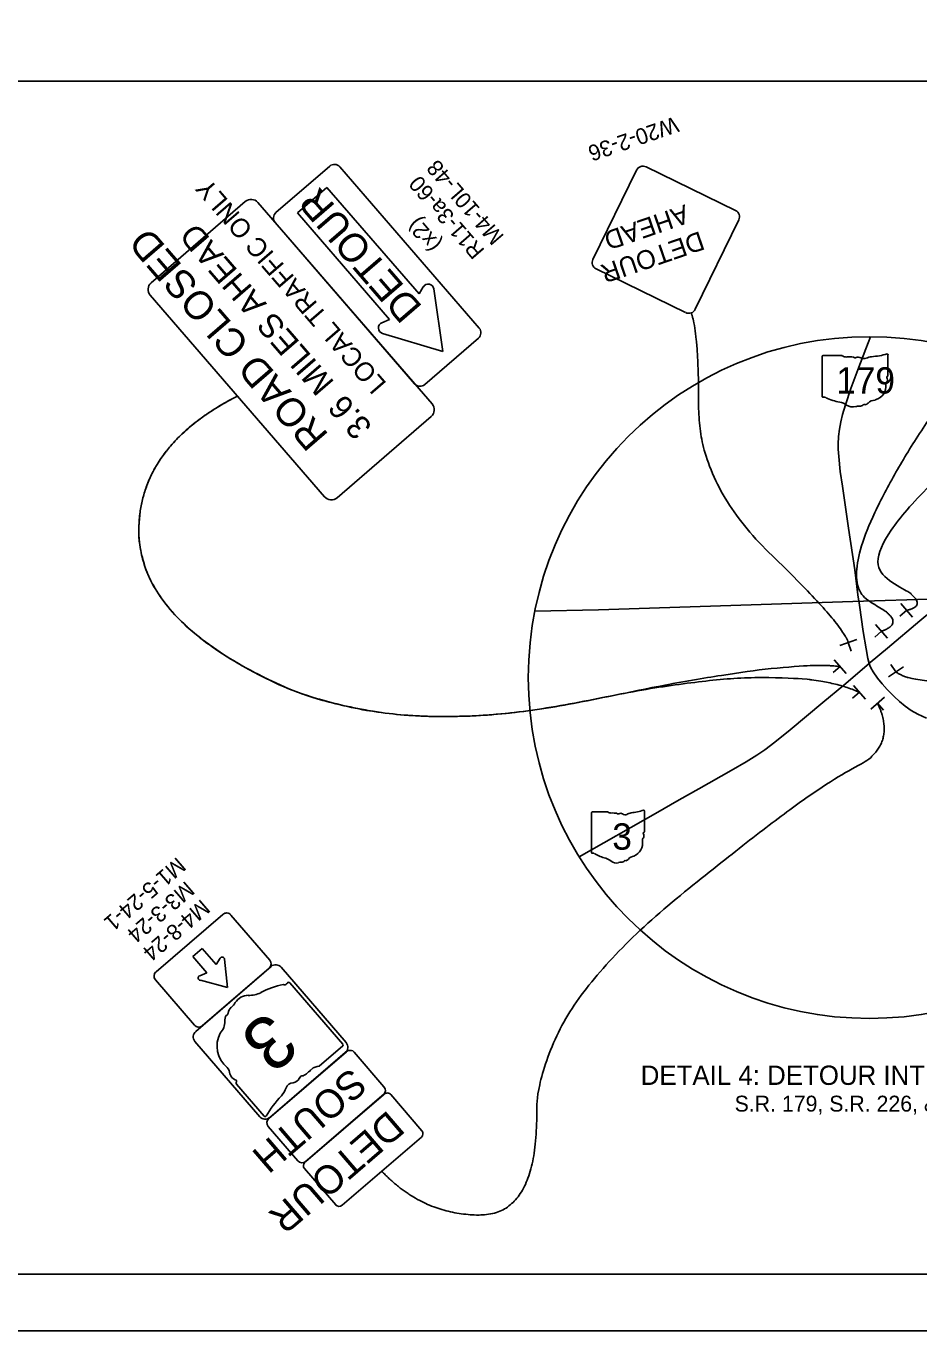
# Model space of a CAD drawing. Extents: x -15.3 to 34, y 0 to 22.
# Drawn here: x 16.96 to 24.81, y 0 to 11.48 of the extents above; entities that cross this region are included whole.
import ezdxf

# ---------------------------------------------------------------- set-up
doc = ezdxf.new("R2010")
doc.units = 0
for name, color, linetype in [('GM_X_State_Route', 7, 'Continuous'), ('GM_X_State_Shield', 7, 'Continuous'), ('GM_X_Township', 7, 'Continuous'), ('SC_Scratch1', 7, 'Continuous'), ('SH_Border', 7, 'Continuous'), ('SH_Cut_Line', 7, 'Continuous'), ('SH_Text', 7, 'Continuous'), ('SN_P_Signs', 7, 'Continuous')]:
    doc.layers.add(name, color=color, linetype=linetype)

msp = doc.modelspace()

# ---------------------------------------------------------------- linework, layer by layer
at = {"layer": 'GM_X_State_Route'}
for points in [[(24.275, 6.479), (24.248, 6.699), (24.193, 7.066), (24.138, 7.434), (24.119, 7.564), (24.106, 7.695), (24.101, 7.761), (24.101, 7.805), (24.104, 7.871), (24.113, 7.937), (24.124, 8.001), (24.14, 8.066), (24.164, 8.15), (24.212, 8.295), (24.273, 8.459), (24.344, 8.643), (24.386, 8.75)], [(24.374, 5.874), (24.362, 5.917), (24.346, 6.003), (24.322, 6.154), (24.289, 6.388), (24.275, 6.479)], [(24.374, 5.874), (24.383, 5.882), (24.534, 6.008), (24.819, 6.248), (25.11, 6.489)], [(21.824, 4.172), (22.493, 4.554), (22.702, 4.674), (22.874, 4.771), (23.159, 4.932), (23.292, 5.008), (23.385, 5.066), (23.456, 5.115), (23.544, 5.181), (23.679, 5.291), (23.965, 5.53), (24.15, 5.683), (24.374, 5.874)], [(24.879, 5.392), (24.801, 5.429), (24.744, 5.461), (24.691, 5.498), (24.64, 5.538), (24.592, 5.582), (24.531, 5.645), (24.488, 5.694), (24.448, 5.745), (24.41, 5.799), (24.388, 5.836), (24.38, 5.855), (24.374, 5.874)]]:
    msp.add_lwpolyline(points, dxfattribs=at)
at = {"layer": 'GM_X_State_Shield'}
for p, q in [((23.959, 8.577), (23.959, 8.224)), ((24.135, 8.583), (23.965, 8.583)), ((24.539, 8.407), (24.539, 8.591)), ((24.539, 8.407), (24.539, 8.407)), ((21.932, 4.563), (21.932, 4.21)), ((22.072, 4.569), (21.936, 4.569)), ((22.396, 4.393), (22.396, 4.577)), ((22.396, 4.393), (22.396, 4.393))]:
    msp.add_line(p, q, dxfattribs=at)
for centre, radius, start, end in [((21.937, 4.563), 0.00538, 98.1301, 188.1301), ((22.104, 4.61), 0.0521, 231.6195, 271.1119), ((22.122, 4.371), 0.187, 80.4867, 94.9883), ((22.164, 4.565), 0.015, 219.7921, 297.1024), ((22.186, 4.524), 0.0313, 54.4667, 119.1411), ((22.227, 4.58), 0.0376, 233.8562, 294.8282), ((22.293, 4.461), 0.099, 97.3462, 120.7689), ((22.23, 5.049), 0.492, 275.8445, 288.9065), ((22.39, 4.578), 0.00517, 351.8621, 97.738), ((22.394, 4.38), 0.00799, 107.944, 210.337), ((22.344, 4.356), 0.048, 340.033, 23.6496), ((22.39, 4.392), 0.00553, 289.6038, 7.7341), ((22.258, 4.293), 0.123, 292.3089, 8.9858), ((22.414, 4.316), 0.0349, 136.8065, 186.9296), ((21.937, 4.21), 0.00542, 171.9584, 258.3066), ((21.938, 4.246), 0.0414, 267.339, 280.6039), ((21.946, 4.19), 0.0149, 29.7484, 93.2717), ((22.135, 4.507), 0.355, 240.4129, 257.1985), ((22.029, 4.052), 0.111, 47.1842, 75.836), ((22.195, 4.162), 0.0376, 268.777, 315.5493), ((22.229, 4.128), 0.0106, 65.7517, 132.6484), ((22.224, 4.176), 0.0398, 282.8732, 323.2771), ((22.31, 4.111), 0.0674, 94.4031, 142.5768), ((22.149, 4.188), 0.0706, 230.7004, 286.2918), ((22.19, 4.067), 0.058, 85.6951, 111.2099)]:
    msp.add_arc(centre, radius, start, end, dxfattribs=at)
for centre, major_axis, start_param, end_param in [((23.966, 8.577), (0.00672, 0), 1.712693, 3.28349), ((24.175, 8.623), (0.0652, 0), 4.042523, 4.731795), ((24.197, 8.385), (0.234, 0), 1.404758, 1.657858), ((24.25, 8.579), (0.0188, 0), 3.836095, 5.185415), ((24.277, 8.538), (0.0391, 0), 0.950623, 2.079405), ((24.328, 8.594), (0.047, 0), 4.081561, 5.145723), ((24.411, 8.475), (0.124, 0), 1.699011, 2.107814), ((24.332, 9.063), (0.615, 0), 4.814394, 5.042369), ((24.533, 8.592), (0.00646, 0), 6.141152, 7.989035), ((24.538, 8.394), (0.00999, 0), 1.883978, 3.671073), ((24.474, 8.37), (0.06, 0), 5.934695, 6.695948), ((24.532, 8.406), (0.00691, 0), 5.05454, 6.418171), ((24.367, 8.307), (0.154, 0), 5.101752, 6.440018), ((24.562, 8.33), (0.0436, 0), 2.387724, 3.262537), ((23.966, 8.224), (0.00678, 0), 3.00124, 4.508301), ((23.967, 8.26), (0.0517, 0), 4.665946, 4.897461), ((23.977, 8.204), (0.0187, 0), 0.519207, 1.627899), ((24.213, 8.52), (0.444, 0), 4.195997, 4.488961), ((24.08, 8.066), (0.139, 0), 0.823519, 1.323587), ((24.331, 8.142), (0.0132, 0), 1.147584, 2.315152), ((24.325, 8.19), (0.0497, 0), 4.937069, 5.64225), ((24.432, 8.125), (0.0843, 0), 1.647645, 2.488434), ((24.231, 8.202), (0.0882, 0), 4.026481, 4.996735), ((24.282, 8.08), (0.0725, 0), 1.495662, 1.94098), ((24.288, 8.176), (0.047, 0), 4.691044, 5.507374)]:
    msp.add_ellipse(centre, major_axis=major_axis, ratio=0.8, start_param=start_param, end_param=end_param, dxfattribs=at)
at = {"layer": 'GM_X_Township'}
msp.add_lwpolyline([(21.433, 6.335), (21.992, 6.347), (24.231, 6.418), (24.989, 6.443), (27.276, 6.515)], dxfattribs=at)
at = {"layer": 'SH_Border'}
msp.add_lwpolyline([(1.5, 21.5), (33.5, 21.5), (33.5, 0.5), (1.5, 0.5)], close=True, dxfattribs=at)
at = {"layer": 'SH_Cut_Line'}
msp.add_lwpolyline([(0, 0), (34, 0), (34, 22), (0, 22)], close=True, dxfattribs=at)
at = {"layer": 'SH_Text'}
msp.add_line((1.5, 11), (32, 11), dxfattribs=at)
msp.add_circle((24.375, 5.75), 3, dxfattribs=at)
for points in [[(22.807, 8.959), (22.874, 8.806), (22.874, 7.45), (24.136, 6.227), (24.19, 6.059)], [(25.691, 8.936), (25.108, 8.44), (24.059, 6.582), (24.722, 6.238), (24.482, 6.158)], [(27.707, 8.067), (27.378, 7.746), (26.619, 8.935), (24.147, 6.818), (24.949, 6.395), (24.704, 6.342)], [(18.817, 8.227), (17.95, 7.785), (17.95, 6.298), (20.187, 5.187), (23.64, 5.914), (24.288, 5.62)], [(18.817, 8.227), (17.95, 7.785), (17.95, 6.298), (20.187, 5.187), (23.64, 5.914), (24.118, 5.846)], [(29.1, 5.444), (28.747, 6.047), (26.796, 6.047), (24.861, 5.622), (24.609, 5.799)], [(20.086, 1.406), (20.45, 1.02), (21.45, 1.02), (21.45, 2.793), (23.851, 4.766), (24.629, 5.139), (24.448, 5.524)]]:
    msp.add_open_spline(points, degree=2, dxfattribs=at)
at = {"layer": 'SN_P_Signs'}
for p, q in [((19.344, 9.84), (19.604, 10.064)), ((19.604, 10.064), (20.415, 9.127)), ((20.154, 8.902), (19.344, 9.84)), ((20.415, 9.127), (20.452, 9.189)), ((20.545, 9.17), (20.625, 8.62)), ((20.087, 8.873), (20.154, 8.902)), ((20.625, 8.62), (20.093, 8.779)), ((24.704, 6.342), (24.643, 6.29)), ((24.652, 6.403), (24.756, 6.282)), ((24.43, 6.218), (24.534, 6.097)), ((24.482, 6.158), (24.422, 6.105)), ((24.114, 6.033), (24.265, 6.085)), ((24.19, 6.059), (24.216, 5.983)), ((24.065, 5.906), (24.17, 5.785)), ((24.609, 5.799), (24.565, 5.866)), ((24.118, 5.846), (24.057, 5.793)), ((24.676, 5.843), (24.543, 5.755)), ((24.235, 5.68), (24.34, 5.559)), ((24.288, 5.62), (24.227, 5.568)), ((24.387, 5.472), (24.508, 5.576)), ((24.448, 5.524), (24.5, 5.463)), ((18.101, 3.16), (18.688, 3.666)), ((18.759, 3.66), (19.101, 3.263)), ((18.424, 3.294), (18.507, 3.366)), ((18.507, 3.366), (18.63, 3.224)), ((18.547, 3.152), (18.424, 3.294)), ((18.63, 3.224), (18.665, 3.281)), ((18.703, 3.272), (18.731, 3.022)), ((18.485, 3.126), (18.547, 3.152)), ((19.096, 3.192), (18.508, 2.686)), ((18.438, 2.692), (18.095, 3.09)), ((18.731, 3.022), (18.492, 3.086)), ((19.743, 2.524), (19.278, 3.064)), ((19.093, 1.87), (19.775, 2.457)), ((19.536, 2.33), (19.744, 2.509)), ((19.845, 2.452), (20.106, 2.149)), ((18.809, 2.172), (19.052, 1.89)), ((18.809, 2.172), (18.809, 2.172)), ((20.101, 2.078), (19.419, 1.491)), ((19.348, 1.496), (19.087, 1.8))]:
    msp.add_line(p, q, dxfattribs=at)
for points in [[(19.629, 10.251), (19.156, 9.842)], [(20.943, 8.826), (19.717, 10.245)], [(22.411, 10.245), (23.198, 9.861)], [(21.944, 9.429), (22.328, 10.216)], [(18.886, 9.94), (18.058, 9.224)], [(20.529, 8.158), (18.996, 9.931)], [(23.226, 9.778), (22.843, 8.991)], [(19.149, 9.754), (20.375, 8.336)], [(22.759, 8.962), (21.973, 9.346)], [(18.05, 9.114), (19.583, 7.341)], [(20.464, 8.329), (20.936, 8.738)], [(19.693, 7.333), (20.521, 8.048)], [(19.113, 3.207), (18.45, 2.636)], [(19.772, 2.537), (19.201, 3.2)], [(18.443, 2.548), (19.014, 1.885)], [(19.102, 1.878), (19.765, 2.449)], [(20.109, 2.085), (19.411, 1.485)], [(20.439, 1.762), (20.165, 2.08)], [(19.738, 1.106), (20.435, 1.706)], [(19.407, 1.428), (19.681, 1.11)]]:
    msp.add_lwpolyline(points, dxfattribs=at)
for centre, radius, start, end in [((19.67, 10.204), 0.0625, 40.8371, 130.8371), ((22.384, 10.188), 0.0625, 63.9999, 153.9999), ((18.937, 9.88), 0.0781, 40.8371, 130.8371), ((19.197, 9.795), 0.0625, 130.8371, 220.8371), ((23.17, 9.805), 0.0625, 333.9999, 63.9999), ((22, 9.402), 0.0625, 153.9999, 243.9999), ((18.109, 9.165), 0.0781, 130.8371, 220.8371), ((20.495, 9.163), 0.05, 8.3263, 148.656), ((22.787, 9.018), 0.0625, 243.9999, 333.9999), ((20.107, 8.827), 0.05, 113.0183, 253.348), ((20.896, 8.785), 0.0625, 310.8371, 40.8371), ((20.423, 8.376), 0.0625, 220.8371, 310.8371), ((20.47, 8.107), 0.0781, 310.8371, 40.8371), ((19.642, 7.392), 0.0781, 220.8371, 310.8371), ((18.721, 3.628), 0.05, 40.7178, 130.7178), ((18.683, 3.269), 0.0209, 6.1291, 147.9224), ((19.063, 3.23), 0.05, 310.7178, 40.7178), ((19.154, 3.16), 0.0625, 40.7178, 130.7178), ((18.133, 3.122), 0.05, 130.7178, 220.7178), ((18.493, 3.106), 0.0209, 113.5132, 265.7274), ((19.358, 2.343), 0.718, 101.1308, 117.9163), ((19.229, 3.076), 0.0302, 250.4662, 313.9896), ((19.315, 3.002), 0.0836, 128.0568, 141.3217), ((19.269, 3.058), 0.011, 32.6762, 119.0245), ((18.694, 2.944), 0.117, 306.413, 331.9278), ((18.917, 2.811), 0.143, 91.4182, 147.0097), ((18.921, 3.178), 0.225, 267.902, 296.5538), ((18.785, 2.73), 0.0803, 143.591, 183.9949), ((18.714, 2.798), 0.0214, 286.4696, 353.3663), ((18.811, 2.791), 0.0759, 129.4949, 176.2671), ((18.476, 2.724), 0.05, 220.7178, 310.7178), ((18.569, 2.717), 0.136, 315.121, 3.2946), ((18.491, 2.589), 0.0625, 130.7178, 220.7178), ((18.887, 2.508), 0.249, 153.0267, 229.7037), ((19.725, 2.496), 0.0625, 310.7178, 40.7178), ((19.735, 2.516), 0.0109, 318.8479, 48.8479), ((19.808, 2.419), 0.05, 40.7178, 130.7178), ((18.679, 2.266), 0.0705, 357.5243, 47.6474), ((19.199, 2.567), 0.378, 301.2045, 315.7061), ((19.54, 2.225), 0.105, 92.3373, 131.8297), ((18.84, 2.297), 0.097, 200.7508, 244.3674), ((18.793, 2.195), 0.0162, 328.6618, 71.0548), ((18.816, 2.181), 0.0112, 150.3216, 228.452), ((19.314, 2.108), 0.076, 94.574, 155.546), ((19.302, 2.247), 0.0632, 275.1845, 339.859), ((19.39, 2.214), 0.0304, 80.5099, 157.8202), ((19.926, 1.386), 0.994, 136.5623, 149.6243), ((19.055, 2.203), 0.2, 318.064, 341.4867), ((20.068, 2.116), 0.05, 310.7178, 40.7178), ((20.135, 2.054), 0.04, 40.7178, 130.7178), ((19.061, 1.926), 0.0625, 220.7178, 310.7178), ((19.06, 1.896), 0.0104, 212.5799, 318.4558), ((19.125, 1.832), 0.05, 130.7178, 220.7178), ((20.409, 1.736), 0.04, 310.7178, 40.7178), ((19.386, 1.529), 0.05, 220.7178, 310.7178), ((19.437, 1.454), 0.04, 130.7178, 220.7178), ((19.711, 1.136), 0.04, 220.7178, 310.7178)]:
    msp.add_arc(centre, radius, start, end, dxfattribs=at)

# ---------------------------------------------------------------- texts
at = {"layer": 'GM_X_State_Shield'}
for s, p in [('179', (24.083, 8.249)), ('3', (22.114, 4.235))]:
    msp.add_text(s, height=0.232, dxfattribs=at).set_placement(p)
at = {"layer": 'SC_Scratch1'}
for s, rotation, p in [('W20-2-36', 198.9999, (22.666, 10.69)), ('M4-10L-48', 130.8371, (21.168, 9.634)), ('R11-3a-60', 130.8371, (20.998, 9.51)), ('M1-5-24-1', 220.7178, (18.286, 4.177)), ('M3-3-24', 220.7178, (18.362, 3.966)), ('M4-8-24', 220.7178, (18.499, 3.806))]:
    msp.add_text(s, height=0.14, rotation=rotation, dxfattribs=at).set_placement(p)
at = {"layer": 'SH_Text'}
msp.add_text('(x2)', height=0.14, rotation=130.8371, dxfattribs=at).set_placement((20.617, 9.568))
for s, height, p in [('DETAIL 4: DETOUR INTERSECTION', 0.17, (22.364, 2.165)), ('S.R. 179, S.R. 226, & S.R .3', 0.14, (23.19, 1.93))]:
    msp.add_text(s, height=height, dxfattribs=at).set_placement(p)
at = {"layer": 'SN_P_Signs'}
for s, height, rotation, p in [('LOCAL TRAFFIC ONLY', 0.16667, 130.8371, (20.135, 8.338)), ('DETOUR', 0.25, 130.8371, (20.451, 9.012)), ('AHEAD', 0.1667, 198.9999, (22.753, 9.915)), ('ROAD CLOSED', 0.25, 130.8371, (19.626, 7.886)), ('MILES AHEAD', 0.20833, 130.8371, (19.677, 8.348)), ('DETOUR', 0.1667, 198.9999, (22.886, 9.681)), ('3.6', 0.2083, 130.8371, (20.011, 7.961)), ('3', 0.469, 220.7178, (19.082, 2.829)), ('SOUTH', 0.25, 220.7178, (19.815, 2.327)), ('DETOUR', 0.25, 220.7178, (20.143, 1.95))]:
    msp.add_text(s, height=height, rotation=rotation, dxfattribs=at).set_placement(p)

doc.saveas('drawing.dxf')
